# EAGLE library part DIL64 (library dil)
SOCKET Dual In Line
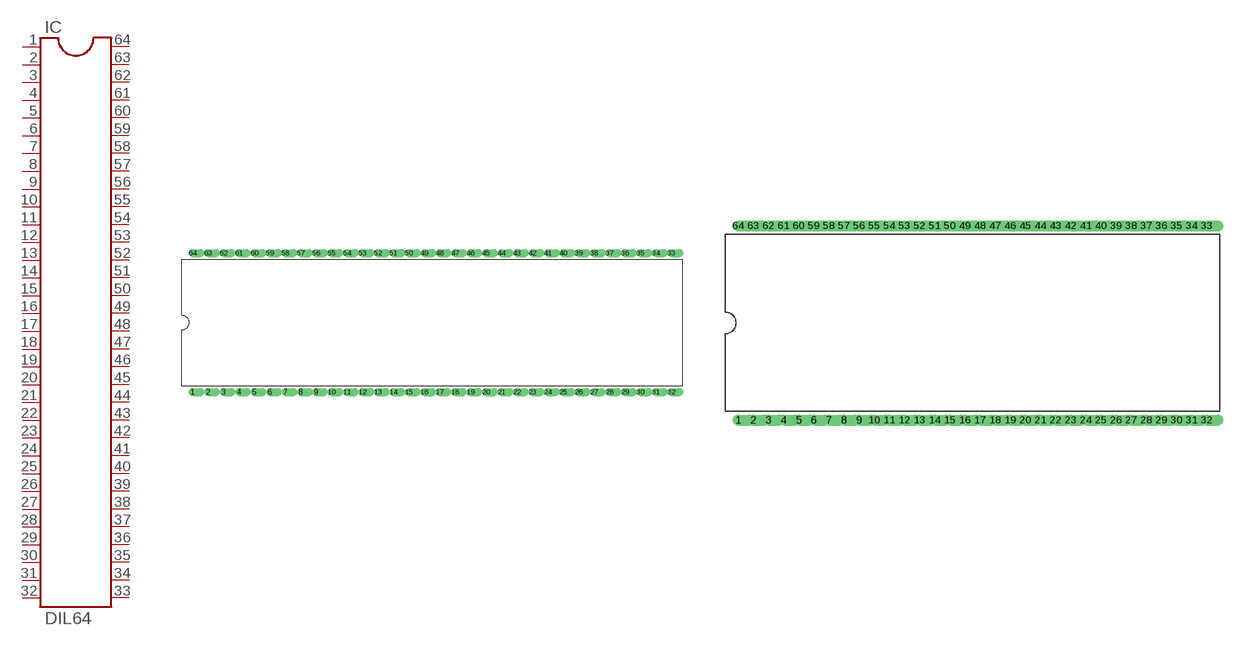
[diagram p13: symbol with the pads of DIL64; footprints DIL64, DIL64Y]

Designator prefix IC

## DIL64  [DIL64]
1  1  pas
2  2  pas
3  3  pas
4  4  pas
5  5  pas
6  6  pas
7  7  pas
8  8  pas
9  9  pas
10  10  pas
11  11  pas
12  12  pas
13  13  pas
14  14  pas
15  15  pas
16  16  pas
17  17  pas
18  18  pas
19  19  pas
20  20  pas
21  21  pas
22  22  pas
23  23  pas
24  24  pas
25  25  pas
26  26  pas
27  27  pas
28  28  pas
29  29  pas
30  30  pas
31  31  pas
32  32  pas
33  33  pas
34  34  pas
35  35  pas
36  36  pas
37  37  pas
38  38  pas
39  39  pas
40  40  pas
41  41  pas
42  42  pas
43  43  pas
44  44  pas
45  45  pas
46  46  pas
47  47  pas
48  48  pas
49  49  pas
50  50  pas
51  51  pas
52  52  pas
53  53  pas
54  54  pas
55  55  pas
56  56  pas
57  57  pas
58  58  pas
59  59  pas
60  60  pas
61  61  pas
62  62  pas
63  63  pas
64  64  pas

## DIL64YL  [DIL64Y]
Pads as for DIL64

## Footprint DIL64 (pad centres in mm)
SOCKET Dual In Line
drill 0.813 offset: 1 -39.37,-11.43; 2 -36.83,-11.43; 3 -34.29,-11.43; 4 -31.75,-11.43; 5 -29.21,-11.43; 6 -26.67,-11.43; 7 -24.13,-11.43; 8 -21.59,-11.43; 9 -19.05,-11.43; 10 -16.51,-11.43; 11 -13.97,-11.43; 12 -11.43,-11.43; 13 -8.89,-11.43; 14 -6.35,-11.43; 15 -3.81,-11.43; 16 -1.27,-11.43; 17 1.27,-11.43; 18 3.81,-11.43; 19 6.35,-11.43; 20 8.89,-11.43; 21 11.43,-11.43; 22 13.97,-11.43; 23 16.51,-11.43; 24 19.05,-11.43; 25 21.59,-11.43; 26 24.13,-11.43; 27 26.67,-11.43; 28 29.21,-11.43; 29 31.75,-11.43; 30 34.29,-11.43; 31 36.83,-11.43; 32 39.37,-11.43; 33 39.37,11.43; 34 36.83,11.43; 35 34.29,11.43; 36 31.75,11.43; 37 29.21,11.43; 38 26.67,11.43; 39 24.13,11.43; 40 21.59,11.43; 41 19.05,11.43; 42 16.51,11.43; 43 13.97,11.43; 44 11.43,11.43; 45 8.89,11.43; 46 6.35,11.43; 47 3.81,11.43; 48 1.27,11.43; 49 -1.27,11.43; 50 -3.81,11.43; 51 -6.35,11.43; 52 -8.89,11.43; 53 -11.43,11.43; 54 -13.97,11.43; 55 -16.51,11.43; 56 -19.05,11.43; 57 -21.59,11.43; 58 -24.13,11.43; 59 -26.67,11.43; 60 -29.21,11.43; 61 -31.75,11.43; 62 -34.29,11.43; 63 -36.83,11.43; 64 -39.37,11.43

## Footprint DIL64Y (pad centres in mm)
SOCKET Dual In Line, elongated pads
drill 0.813 offset: 1 -27.559,-11.43; 2 -25.781,-11.43; 3 -24.003,-11.43; 4 -22.225,-11.43; 5 -20.447,-11.43; 6 -18.669,-11.43; 7 -16.891,-11.43; 8 -15.113,-11.43; 9 -13.335,-11.43; 10 -11.557,-11.43; 11 -9.779,-11.43; 12 -8.001,-11.43; 13 -6.223,-11.43; 14 -4.445,-11.43; 15 -2.667,-11.43; 16 -0.889,-11.43; 17 0.889,-11.43; 18 2.667,-11.43; 19 4.445,-11.43; 20 6.223,-11.43; 21 8.001,-11.43; 22 9.779,-11.43; 23 11.557,-11.43; 24 13.335,-11.43; 25 15.113,-11.43; 26 16.891,-11.43; 27 18.669,-11.43; 28 20.447,-11.43; 29 22.225,-11.43; 30 24.003,-11.43; 31 25.781,-11.43; 32 27.559,-11.43; 33 27.559,11.43; 34 25.781,11.43; 35 24.003,11.43; 36 22.225,11.43; 37 20.447,11.43; 38 18.669,11.43; 39 16.891,11.43; 40 15.113,11.43; 41 13.335,11.43; 42 11.557,11.43; 43 9.779,11.43; 44 8.001,11.43; 45 6.223,11.43; 46 4.445,11.43; 47 2.667,11.43; 48 0.889,11.43; 49 -0.889,11.43; 50 -2.667,11.43; 51 -4.445,11.43; 52 -6.223,11.43; 53 -8.001,11.43; 54 -9.779,11.43; 55 -11.557,11.43; 56 -13.335,11.43; 57 -15.113,11.43; 58 -16.891,11.43; 59 -18.669,11.43; 60 -20.447,11.43; 61 -22.225,11.43; 62 -24.003,11.43; 63 -25.781,11.43; 64 -27.559,11.43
